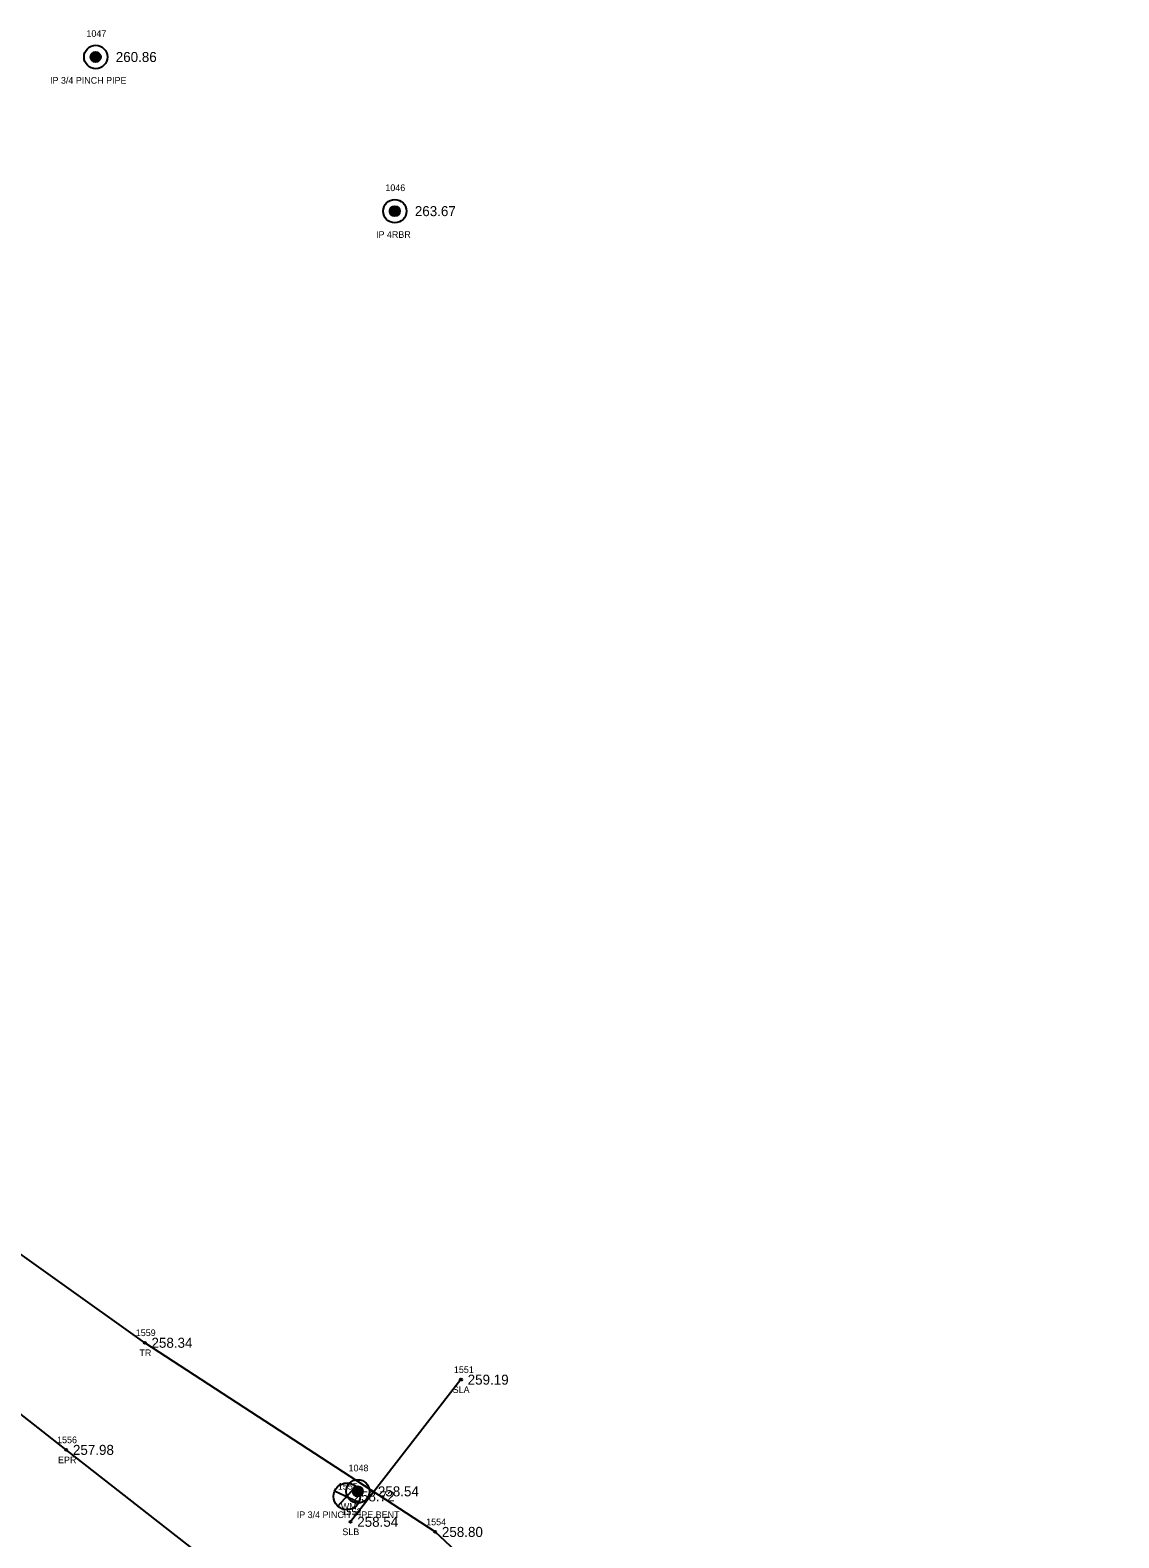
# Model space of a CAD drawing. Extents: x 1961231 to 1962574, y 799865 to 801120.
# Drawn here: x 1961547.5 to 1961710.5, y 800894.4 to 801120 of the extents above; entities that cross this region are included whole.
import ezdxf

# ---------------------------------------------------------------- set-up
doc = ezdxf.new("R2010")
doc.units = 0
for name, color, linetype in [('RD_EX_DV_Prop_txCode', 7, 'Continuous'), ('RD_EX_DV_PropPin', 7, 'Continuous'), ('RD_EX_Road', 7, 'Continuous'), ('RD_EX_Road_txCode', 7, 'Continuous'), ('RD_EX_TX_DV_Prop_ELEV', 7, 'Continuous'), ('RD_EX_TX_Road_ELEV', 7, 'Continuous'), ('RD_EX_TX_UT_ELEV', 7, 'Continuous'), ('RD_EX_TX_VEG_ELEV', 7, 'Continuous'), ('RD_EX_UT', 7, 'Continuous'), ('RD_EX_UT_txCode', 7, 'Continuous'), ('RD_EX_VEG', 7, 'Continuous'), ('RD_EX_VEG_txCode', 7, 'Continuous'), ('RD_SMD_Locator', 7, 'Continuous')]:
    doc.layers.add(name, color=color, linetype=linetype)

msp = doc.modelspace()

# ---------------------------------------------------------------- linework, layer by layer
at = {"layer": 'RD_EX_DV_PropPin'}
for p, q in [((1961556.57, 801115.82), (1961556.57, 801116.21)), ((1961556.61, 801115.72), (1961556.61, 801116.31)), ((1961556.64, 801115.64), (1961556.64, 801116.38)), ((1961556.68, 801115.59), (1961556.68, 801116.44)), ((1961556.71, 801115.54), (1961556.71, 801116.49)), ((1961556.75, 801115.5), (1961556.75, 801116.53)), ((1961556.78, 801115.46), (1961556.78, 801116.56)), ((1961556.82, 801115.43), (1961556.82, 801116.6)), ((1961556.85, 801115.4), (1961556.85, 801116.62)), ((1961556.89, 801115.38), (1961556.89, 801116.65)), ((1961556.92, 801115.36), (1961556.92, 801116.67)), ((1961556.96, 801115.34), (1961556.96, 801116.69)), ((1961556.99, 801115.32), (1961556.99, 801116.71)), ((1961557.03, 801115.31), (1961557.03, 801116.72)), ((1961557.06, 801115.29), (1961557.06, 801116.73)), ((1961557.1, 801115.28), (1961557.1, 801116.74)), ((1961557.13, 801115.27), (1961557.13, 801116.75)), ((1961557.17, 801115.27), (1961557.17, 801116.76)), ((1961557.2, 801115.26), (1961557.2, 801116.77)), ((1961557.24, 801115.26), (1961557.24, 801116.77)), ((1961557.27, 801115.25), (1961557.27, 801116.77)), ((1961557.31, 801115.25), (1961557.31, 801116.77)), ((1961557.34, 801115.25), (1961557.34, 801116.77)), ((1961557.38, 801115.26), (1961557.38, 801116.77)), ((1961557.41, 801115.26), (1961557.41, 801116.77)), ((1961557.45, 801115.27), (1961557.45, 801116.76)), ((1961557.48, 801115.27), (1961557.48, 801116.75)), ((1961557.52, 801115.28), (1961557.52, 801116.74)), ((1961557.55, 801115.29), (1961557.55, 801116.73)), ((1961557.59, 801115.31), (1961557.59, 801116.72)), ((1961557.62, 801115.32), (1961557.62, 801116.71)), ((1961557.66, 801115.34), (1961557.66, 801116.69)), ((1961557.69, 801115.36), (1961557.69, 801116.67)), ((1961557.73, 801115.38), (1961557.73, 801116.65)), ((1961557.76, 801115.4), (1961557.76, 801116.62)), ((1961557.8, 801115.43), (1961557.8, 801116.6)), ((1961557.83, 801115.46), (1961557.83, 801116.56)), ((1961557.87, 801115.5), (1961557.87, 801116.53)), ((1961557.9, 801115.54), (1961557.9, 801116.49)), ((1961557.94, 801115.59), (1961557.94, 801116.44)), ((1961557.97, 801115.64), (1961557.97, 801116.38)), ((1961558.01, 801115.72), (1961558.01, 801116.31)), ((1961558.04, 801115.82), (1961558.04, 801116.21)), ((1961601.42, 801092.57), (1961601.42, 801093.31)), ((1961601.45, 801092.51), (1961601.45, 801093.37)), ((1961601.49, 801092.47), (1961601.49, 801093.42)), ((1961601.52, 801092.43), (1961601.52, 801093.46)), ((1961601.56, 801092.39), (1961601.56, 801093.49)), ((1961601.59, 801092.36), (1961601.59, 801093.52)), ((1961601.63, 801092.33), (1961601.63, 801093.55)), ((1961601.66, 801092.31), (1961601.66, 801093.58)), ((1961601.7, 801092.29), (1961601.7, 801093.6)), ((1961601.73, 801092.27), (1961601.73, 801093.62)), ((1961601.77, 801092.25), (1961601.77, 801093.63)), ((1961601.8, 801092.23), (1961601.8, 801093.65)), ((1961601.84, 801092.22), (1961601.84, 801093.66)), ((1961601.87, 801092.21), (1961601.87, 801093.67)), ((1961601.91, 801092.2), (1961601.91, 801093.68)), ((1961601.94, 801092.19), (1961601.94, 801093.69)), ((1961601.98, 801092.19), (1961601.98, 801093.7)), ((1961602.01, 801092.18), (1961602.01, 801093.7)), ((1961602.05, 801092.18), (1961602.05, 801093.7)), ((1961602.08, 801092.18), (1961602.08, 801093.7)), ((1961602.12, 801092.18), (1961602.12, 801093.7)), ((1961602.15, 801092.18), (1961602.15, 801093.7)), ((1961602.19, 801092.19), (1961602.19, 801093.7)), ((1961602.22, 801092.19), (1961602.22, 801093.69)), ((1961602.26, 801092.2), (1961602.26, 801093.68)), ((1961602.29, 801092.21), (1961602.29, 801093.67)), ((1961602.33, 801092.22), (1961602.33, 801093.66)), ((1961602.36, 801092.23), (1961602.36, 801093.65)), ((1961602.4, 801092.25), (1961602.4, 801093.63)), ((1961602.43, 801092.27), (1961602.43, 801093.62)), ((1961602.47, 801092.29), (1961602.47, 801093.6)), ((1961602.5, 801092.31), (1961602.5, 801093.58)), ((1961602.54, 801092.33), (1961602.54, 801093.55)), ((1961602.57, 801092.36), (1961602.57, 801093.52)), ((1961602.61, 801092.39), (1961602.61, 801093.49)), ((1961602.64, 801092.43), (1961602.64, 801093.46)), ((1961602.68, 801092.47), (1961602.68, 801093.42)), ((1961602.71, 801092.51), (1961602.71, 801093.37)), ((1961602.75, 801092.57), (1961602.75, 801093.31)), ((1961601.35, 801092.75), (1961601.35, 801093.14)), ((1961601.38, 801092.64), (1961601.38, 801093.24)), ((1961602.78, 801092.64), (1961602.78, 801093.24)), ((1961602.82, 801092.75), (1961602.82, 801093.14)), ((1961595.81, 800901.14), (1961595.81, 800901.53)), ((1961595.85, 800901.04), (1961595.85, 800901.63)), ((1961595.88, 800900.97), (1961595.88, 800901.7)), ((1961595.92, 800900.91), (1961595.92, 800901.76)), ((1961595.95, 800900.86), (1961595.95, 800901.81)), ((1961595.99, 800900.82), (1961595.99, 800901.85)), ((1961596.02, 800900.78), (1961596.02, 800901.89)), ((1961596.06, 800900.75), (1961596.06, 800901.92)), ((1961596.09, 800900.73), (1961596.09, 800901.94)), ((1961596.13, 800900.7), (1961596.13, 800901.97)), ((1961596.16, 800900.68), (1961596.16, 800901.99)), ((1961596.2, 800900.66), (1961596.2, 800902.01)), ((1961596.23, 800900.64), (1961596.23, 800902.03)), ((1961596.27, 800900.63), (1961596.27, 800902.04)), ((1961596.3, 800900.61), (1961596.3, 800902.06)), ((1961596.34, 800900.6), (1961596.34, 800902.07)), ((1961596.37, 800900.59), (1961596.37, 800902.08)), ((1961596.41, 800900.59), (1961596.41, 800902.08)), ((1961596.44, 800900.58), (1961596.44, 800902.09)), ((1961596.48, 800900.58), (1961596.48, 800902.09)), ((1961596.51, 800900.57), (1961596.51, 800902.1)), ((1961596.55, 800900.57), (1961596.55, 800902.1)), ((1961596.58, 800900.57), (1961596.58, 800902.1)), ((1961596.62, 800900.58), (1961596.62, 800902.09)), ((1961596.65, 800900.58), (1961596.65, 800902.09)), ((1961596.69, 800900.59), (1961596.69, 800902.08)), ((1961596.72, 800900.59), (1961596.72, 800902.08)), ((1961596.76, 800900.6), (1961596.76, 800902.07)), ((1961596.79, 800900.61), (1961596.79, 800902.06)), ((1961596.83, 800900.63), (1961596.83, 800902.04)), ((1961596.86, 800900.64), (1961596.86, 800902.03)), ((1961596.9, 800900.66), (1961596.9, 800902.01)), ((1961596.93, 800900.68), (1961596.93, 800901.99)), ((1961596.97, 800900.7), (1961596.97, 800901.97)), ((1961597, 800900.73), (1961597, 800901.94)), ((1961597.04, 800900.75), (1961597.04, 800901.92)), ((1961597.07, 800900.78), (1961597.07, 800901.89)), ((1961597.11, 800900.82), (1961597.11, 800901.85)), ((1961597.14, 800900.86), (1961597.14, 800901.81)), ((1961597.18, 800900.91), (1961597.18, 800901.76)), ((1961597.21, 800900.97), (1961597.21, 800901.7)), ((1961597.25, 800901.04), (1961597.25, 800901.63)), ((1961597.28, 800901.14), (1961597.28, 800901.53))]:
    msp.add_line(p, q, dxfattribs=at)
for centre, radius in [((1961557.31, 801116.01), 1.75), ((1961557.31, 801116.01), 0.761), ((1961602.08, 801092.94), 1.75), ((1961602.08, 801092.94), 0.761), ((1961596.55, 800901.33), 1.75), ((1961596.55, 800901.33), 0.761)]:
    msp.add_circle(centre, radius, dxfattribs=at)
at = {"layer": 'RD_EX_Road'}
msp.add_lwpolyline([(1961735.63, 800762.82), (1961702.92, 800788.52), (1961676.16, 800810.27), (1961651.45, 800830.73), (1961641.14, 800839.02), (1961595.18, 800874.45), (1961552.9, 800907.54), (1961510.92, 800940.49), (1961504.01, 800946.58), (1961476.53, 800968.16), (1961444.88, 800992.72), (1961406.41, 801021.23), (1961370.69, 801045.26)], dxfattribs=at)
at = {"layer": 'RD_EX_UT'}
for p, q in [((1961593.55, 800899.12), (1961596.22, 800902.02)), ((1961593.07, 800901.42), (1961596.7, 800899.7))]:
    msp.add_line(p, q, dxfattribs=at)
msp.add_circle((1961594.91, 800900.58), 2, dxfattribs=at)
at = {"layer": 'RD_EX_VEG'}
msp.add_line((1961611.99, 800918.05), (1961595.46, 800896.78), dxfattribs=at)
msp.add_lwpolyline([(1961789.73, 800785.49), (1961758.16, 800795.77), (1961726.49, 800818.25), (1961689.15, 800828.3), (1961645.31, 800860.5), (1961608.13, 800895.26), (1961564.66, 800923.57), (1961511.61, 800961.39)], dxfattribs=at)
at = {"layer": 'RD_SMD_Locator'}
for centre in [(1961557.31, 801116.01), (1961602.08, 801092.94), (1961564.66, 800923.57), (1961611.99, 800918.05), (1961552.9, 800907.54), (1961596.55, 800901.33), (1961594.91, 800900.58), (1961595.46, 800896.78), (1961608.13, 800895.26)]:
    msp.add_circle(centre, 0.15, dxfattribs=at)

# ---------------------------------------------------------------- texts
at = {"layer": 'RD_EX_DV_Prop_txCode'}
for s, p in [('1047', (1961555.92, 801119.01)), ('IP 3/4 PINCH PIPE', (1961550.47, 801112.01)), ('1046', (1961600.67, 801095.94)), ('IP 4RBR', (1961599.27, 801088.94)), ('1048', (1961595.16, 800904.33)), ('IP 3/4 PINCH PIPE BENT', (1961587.4, 800897.33))]:
    msp.add_text(s, height=1, dxfattribs=at).set_placement(p)
at = {"layer": 'RD_EX_Road_txCode'}
for s, p in [('1556', (1961551.53, 800908.54)), ('EPR', (1961551.67, 800905.54))]:
    msp.add_text(s, height=1, dxfattribs=at).set_placement(p)
at = {"layer": 'RD_EX_TX_DV_Prop_ELEV'}
for s, p in [('260.86', (1961560.31, 801115.26)), ('263.67', (1961605.08, 801092.19)), ('258.54', (1961599.55, 800900.58))]:
    msp.add_text(s, height=1.5, dxfattribs=at).set_placement(p)
at = {"layer": 'RD_EX_TX_Road_ELEV'}
msp.add_text('257.98', height=1.5, dxfattribs=at).set_placement((1961553.9, 800906.79))
at = {"layer": 'RD_EX_TX_UT_ELEV'}
msp.add_text('258.72', height=1.5, dxfattribs=at).set_placement((1961595.91, 800899.83))
at = {"layer": 'RD_EX_TX_VEG_ELEV'}
for s, p in [('258.34', (1961565.66, 800922.82)), ('259.19', (1961612.99, 800917.3)), ('258.54', (1961596.46, 800896.03)), ('258.80', (1961609.13, 800894.51))]:
    msp.add_text(s, height=1.5, dxfattribs=at).set_placement(p)
at = {"layer": 'RD_EX_UT_txCode'}
for s, p in [('1555', (1961593.56, 800901.58)), ('WM', (1961594, 800898.58))]:
    msp.add_text(s, height=1, dxfattribs=at).set_placement(p)
at = {"layer": 'RD_EX_VEG_txCode'}
for s, p in [('1559', (1961563.31, 800924.57)), ('TR', (1961563.86, 800921.57)), ('1551', (1961610.93, 800919.05)), ('SLA', (1961610.74, 800916.05)), ('1552', (1961594.11, 800897.78)), ('1554', (1961606.78, 800896.26)), ('SLB', (1961594.23, 800894.78))]:
    msp.add_text(s, height=1, dxfattribs=at).set_placement(p)

doc.saveas('drawing.dxf')
